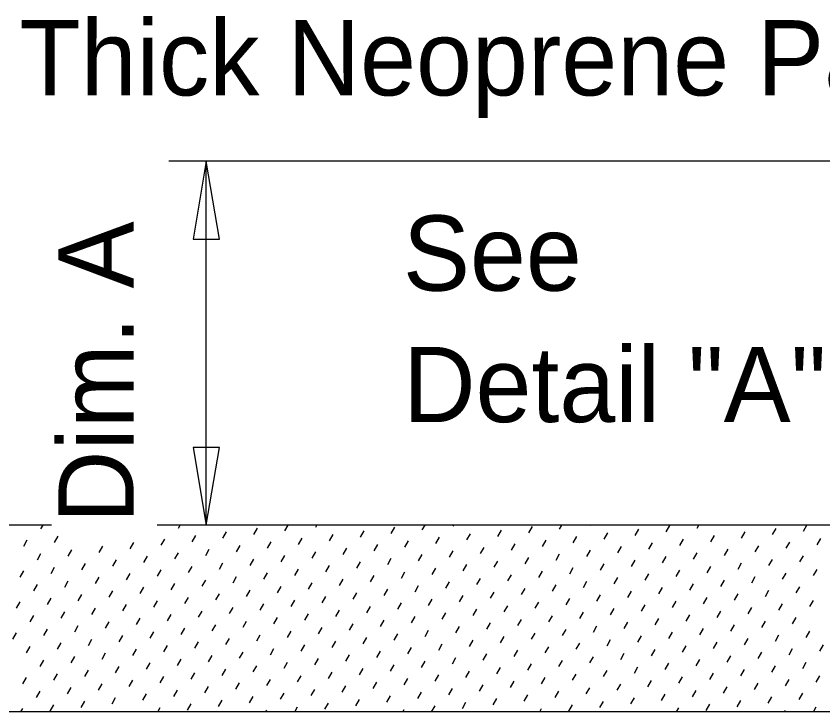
# Model space of a CAD drawing. Extents: x 21516.9 to 21589, y 56156.6 to 56194.3.
# Drawn here: x 21522.743 to 21524.906, y 56182.712 to 56184.575 of the extents above; entities that cross this region are included whole.
import ezdxf

# ---------------------------------------------------------------- set-up
doc = ezdxf.new("R2010")
doc.units = 0
for name, color, linetype in [('AdhocPoint_dp', 7, 'Continuous'), ('Patterning', 7, 'Continuous'), ('PlotBorder_dp', 7, 'Continuous'), ('SheetBorder_dp', 7, 'Continuous')]:
    doc.layers.add(name, color=color, linetype=linetype)

msp = doc.modelspace()

# ---------------------------------------------------------------- linework, layer by layer
at = {"layer": 'AdhocPoint_dp'}
msp.add_line((21525.5524, 56182.7117), (21521.6191, 56182.7117), dxfattribs=at)
at = {"layer": 'Patterning'}
for p, q in [((21522.8378, 56183.2117), (21521.6191, 56183.2117)), ((21522.8099, 56183.2019), (21522.8156, 56183.2117)), ((21525.6112, 56183.2117), (21523.1214, 56183.2117)), ((21523.1783, 56183.2041), (21523.1827, 56183.2117)), ((21523.3808, 56183.187), (21523.3905, 56183.2038)), ((21523.4637, 56183.1967), (21523.4724, 56183.2117)), ((21523.5466, 56183.2064), (21523.5497, 56183.2117)), ((21523.7491, 56183.1893), (21523.7588, 56183.2061)), ((21523.8321, 56183.199), (21523.8394, 56183.2117)), ((21523.915, 56183.2087), (21523.9167, 56183.2117)), ((21524.1175, 56183.1915), (21524.1272, 56183.2083)), ((21524.2004, 56183.2013), (21524.2065, 56183.2117)), ((21524.2833, 56183.211), (21524.2838, 56183.2117)), ((21524.4858, 56183.1938), (21524.4956, 56183.2106)), ((21524.5688, 56183.2035), (21524.5735, 56183.2117)), ((21524.7713, 56183.1864), (21524.781, 56183.2032)), ((21524.8542, 56183.1961), (21524.8632, 56183.2117)), ((21522.8465, 56183.1652), (21522.8562, 56183.182)), ((21523.2149, 56183.1675), (21523.2246, 56183.1843)), ((21523.2978, 56183.1773), (21523.3075, 56183.194)), ((21523.5832, 56183.1698), (21523.593, 56183.1866)), ((21523.6662, 56183.1795), (21523.6759, 56183.1963)), ((21523.9516, 56183.1721), (21523.9613, 56183.1889)), ((21524.0345, 56183.1818), (21524.0443, 56183.1986)), ((21524.237, 56183.1647), (21524.2467, 56183.1814)), ((21524.32, 56183.1744), (21524.3297, 56183.1912)), ((21524.4029, 56183.1841), (21524.4126, 56183.2009)), ((21524.6054, 56183.1669), (21524.6151, 56183.1837)), ((21524.6883, 56183.1767), (21524.698, 56183.1935)), ((21522.7636, 56183.1555), (21522.7733, 56183.1723)), ((21523.049, 56183.1481), (21523.0587, 56183.1649)), ((21523.1319, 56183.1578), (21523.1417, 56183.1746)), ((21523.4174, 56183.1504), (21523.4271, 56183.1672)), ((21523.5003, 56183.1601), (21523.51, 56183.1769)), ((21523.7028, 56183.1429), (21523.7125, 56183.1597)), ((21523.7857, 56183.1526), (21523.7954, 56183.1694)), ((21523.8687, 56183.1624), (21523.8784, 56183.1792)), ((21524.0711, 56183.1452), (21524.0809, 56183.162)), ((21524.1541, 56183.1549), (21524.1638, 56183.1717)), ((21524.4395, 56183.1475), (21524.4492, 56183.1643)), ((21524.5224, 56183.1572), (21524.5322, 56183.174)), ((21524.8079, 56183.1498), (21524.8176, 56183.1666)), ((21524.8908, 56183.1595), (21524.9005, 56183.1763)), ((21522.8831, 56183.1286), (21522.8929, 56183.1454)), ((21522.9661, 56183.1384), (21522.9758, 56183.1552)), ((21523.1685, 56183.1212), (21523.1783, 56183.138)), ((21523.2515, 56183.1309), (21523.2612, 56183.1477)), ((21523.3344, 56183.1406), (21523.3441, 56183.1574)), ((21523.5369, 56183.1235), (21523.5466, 56183.1403)), ((21523.6198, 56183.1332), (21523.6296, 56183.15)), ((21523.9053, 56183.1258), (21523.915, 56183.1426)), ((21523.9882, 56183.1355), (21523.9979, 56183.1523)), ((21524.2736, 56183.128), (21524.2833, 56183.1448)), ((21524.3566, 56183.1378), (21524.3663, 56183.1546)), ((21524.559, 56183.1206), (21524.5688, 56183.1374)), ((21524.642, 56183.1303), (21524.6517, 56183.1471)), ((21524.7249, 56183.1401), (21524.7346, 56183.1568)), ((21522.8002, 56183.1189), (21522.8099, 56183.1357)), ((21523.0027, 56183.1018), (21523.0124, 56183.1185)), ((21523.0856, 56183.1115), (21523.0953, 56183.1283)), ((21523.371, 56183.104), (21523.3808, 56183.1208)), ((21523.454, 56183.1138), (21523.4637, 56183.1306)), ((21523.7394, 56183.1063), (21523.7491, 56183.1231)), ((21523.8223, 56183.116), (21523.8321, 56183.1328)), ((21524.0248, 56183.0989), (21524.0345, 56183.1157)), ((21524.1077, 56183.1086), (21524.1175, 56183.1254)), ((21524.1907, 56183.1183), (21524.2004, 56183.1351)), ((21524.3932, 56183.1012), (21524.4029, 56183.118)), ((21524.4761, 56183.1109), (21524.4858, 56183.1277)), ((21524.7615, 56183.1034), (21524.7713, 56183.1202)), ((21524.8445, 56183.1132), (21524.8542, 56183.13)), ((21522.8368, 56183.0823), (21522.8465, 56183.0991)), ((21522.9197, 56183.092), (21522.9295, 56183.1088)), ((21523.2052, 56183.0846), (21523.2149, 56183.1014)), ((21523.2881, 56183.0943), (21523.2978, 56183.1111)), ((21523.4906, 56183.0772), (21523.5003, 56183.0939)), ((21523.5735, 56183.0869), (21523.5832, 56183.1037)), ((21523.6565, 56183.0966), (21523.6662, 56183.1134)), ((21523.8589, 56183.0794), (21523.8687, 56183.0962)), ((21523.9419, 56183.0892), (21523.9516, 56183.106)), ((21524.2273, 56183.0817), (21524.237, 56183.0985)), ((21524.3102, 56183.0914), (21524.32, 56183.1082)), ((21524.5957, 56183.084), (21524.6054, 56183.1008)), ((21524.6786, 56183.0937), (21524.6883, 56183.1105)), ((21524.8811, 56183.0766), (21524.8908, 56183.0934)), ((21522.7539, 56183.0726), (21522.7636, 56183.0894)), ((21522.9563, 56183.0554), (21522.9661, 56183.0722)), ((21523.0393, 56183.0651), (21523.049, 56183.0819)), ((21523.1222, 56183.0749), (21523.1319, 56183.0917)), ((21523.3247, 56183.0577), (21523.3344, 56183.0745)), ((21523.4076, 56183.0674), (21523.4174, 56183.0842)), ((21523.6931, 56183.06), (21523.7028, 56183.0768)), ((21523.776, 56183.0697), (21523.7857, 56183.0865)), ((21524.0614, 56183.0623), (21524.0711, 56183.0791)), ((21524.1444, 56183.072), (21524.1541, 56183.0888)), ((21524.3468, 56183.0548), (21524.3566, 56183.0716)), ((21524.4298, 56183.0646), (21524.4395, 56183.0813)), ((21524.5127, 56183.0743), (21524.5224, 56183.0911)), ((21524.7152, 56183.0571), (21524.7249, 56183.0739)), ((21524.7981, 56183.0668), (21524.8079, 56183.0836)), ((21522.7905, 56183.036), (21522.8002, 56183.0528)), ((21522.8734, 56183.0457), (21522.8831, 56183.0625)), ((21523.1588, 56183.0383), (21523.1685, 56183.0551)), ((21523.2418, 56183.048), (21523.2515, 56183.0648)), ((21523.5272, 56183.0405), (21523.5369, 56183.0573)), ((21523.6101, 56183.0503), (21523.6198, 56183.0671)), ((21523.8955, 56183.0428), (21523.9053, 56183.0596)), ((21523.9785, 56183.0525), (21523.9882, 56183.0693)), ((21524.181, 56183.0354), (21524.1907, 56183.0522)), ((21524.2639, 56183.0451), (21524.2736, 56183.0619)), ((21524.5493, 56183.0377), (21524.559, 56183.0545)), ((21524.6323, 56183.0474), (21524.642, 56183.0642)), ((21522.993, 56183.0188), (21523.0027, 56183.0356)), ((21523.0759, 56183.0285), (21523.0856, 56183.0453)), ((21523.3613, 56183.0211), (21523.371, 56183.0379)), ((21523.4442, 56183.0308), (21523.454, 56183.0476)), ((21523.6467, 56183.0137), (21523.6565, 56183.0305)), ((21523.7297, 56183.0234), (21523.7394, 56183.0402)), ((21523.8126, 56183.0331), (21523.8223, 56183.0499)), ((21524.0151, 56183.0159), (21524.0248, 56183.0327)), ((21524.098, 56183.0257), (21524.1077, 56183.0425)), ((21524.3834, 56183.0182), (21524.3932, 56183.035)), ((21524.4664, 56183.0279), (21524.4761, 56183.0447)), ((21524.7518, 56183.0205), (21524.7615, 56183.0373)), ((21524.8347, 56183.0302), (21524.8445, 56183.047)), ((21522.8271, 56182.9994), (21522.8368, 56183.0162)), ((21522.91, 56183.0091), (21522.9197, 56183.0259)), ((21523.1125, 56182.9919), (21523.1222, 56183.0087)), ((21523.1954, 56183.0017), (21523.2052, 56183.0184)), ((21523.2784, 56183.0114), (21523.2881, 56183.0282)), ((21523.4809, 56182.9942), (21523.4906, 56183.011)), ((21523.5638, 56183.0039), (21523.5735, 56183.0207)), ((21523.8492, 56182.9965), (21523.8589, 56183.0133)), ((21523.9322, 56183.0062), (21523.9419, 56183.023)), ((21524.2176, 56182.9988), (21524.2273, 56183.0156)), ((21524.3005, 56183.0085), (21524.3102, 56183.0253)), ((21524.503, 56182.9913), (21524.5127, 56183.0081)), ((21524.5859, 56183.0011), (21524.5957, 56183.0179)), ((21524.6689, 56183.0108), (21524.6786, 56183.0276)), ((21524.8713, 56182.9936), (21524.8811, 56183.0104)), ((21522.7441, 56182.9896), (21522.7539, 56183.0064)), ((21522.9466, 56182.9725), (21522.9563, 56182.9893)), ((21523.0296, 56182.9822), (21523.0393, 56182.999)), ((21523.315, 56182.9748), (21523.3247, 56182.9916)), ((21523.3979, 56182.9845), (21523.4076, 56183.0013)), ((21523.6833, 56182.9771), (21523.6931, 56182.9938)), ((21523.7663, 56182.9868), (21523.776, 56183.0036)), ((21523.9688, 56182.9696), (21523.9785, 56182.9864)), ((21524.0517, 56182.9793), (21524.0614, 56182.9961)), ((21524.1346, 56182.9891), (21524.1444, 56183.0059)), ((21524.3371, 56182.9719), (21524.3468, 56182.9887)), ((21524.4201, 56182.9816), (21524.4298, 56182.9984)), ((21524.7055, 56182.9742), (21524.7152, 56182.991)), ((21524.7884, 56182.9839), (21524.7981, 56183.0007)), ((21522.7807, 56182.953), (21522.7905, 56182.9698)), ((21522.8637, 56182.9628), (21522.8734, 56182.9796)), ((21523.1491, 56182.9553), (21523.1588, 56182.9721)), ((21523.232, 56182.965), (21523.2418, 56182.9818)), ((21523.4345, 56182.9479), (21523.4442, 56182.9647)), ((21523.5175, 56182.9576), (21523.5272, 56182.9744)), ((21523.6004, 56182.9673), (21523.6101, 56182.9841)), ((21523.8029, 56182.9502), (21523.8126, 56182.967)), ((21523.8858, 56182.9599), (21523.8955, 56182.9767)), ((21524.1712, 56182.9525), (21524.181, 56182.9692)), ((21524.2542, 56182.9622), (21524.2639, 56182.979)), ((21524.5396, 56182.9547), (21524.5493, 56182.9715)), ((21524.6225, 56182.9645), (21524.6323, 56182.9812)), ((21524.825, 56182.9473), (21524.8347, 56182.9641)), ((21522.9003, 56182.9262), (21522.91, 56182.9429)), ((21522.9832, 56182.9359), (21522.993, 56182.9527)), ((21523.0662, 56182.9456), (21523.0759, 56182.9624)), ((21523.2686, 56182.9284), (21523.2784, 56182.9452)), ((21523.3516, 56182.9382), (21523.3613, 56182.955)), ((21523.637, 56182.9307), (21523.6467, 56182.9475)), ((21523.7199, 56182.9404), (21523.7297, 56182.9572)), ((21524.0054, 56182.933), (21524.0151, 56182.9498)), ((21524.0883, 56182.9427), (21524.098, 56182.9595)), ((21524.2908, 56182.9256), (21524.3005, 56182.9424)), ((21524.3737, 56182.9353), (21524.3834, 56182.9521)), ((21524.4567, 56182.945), (21524.4664, 56182.9618)), ((21524.6591, 56182.9278), (21524.6689, 56182.9446)), ((21524.7421, 56182.9376), (21524.7518, 56182.9544)), ((21522.7344, 56182.9067), (21522.7441, 56182.9235)), ((21522.8174, 56182.9164), (21522.8271, 56182.9332)), ((21523.1028, 56182.909), (21523.1125, 56182.9258)), ((21523.1857, 56182.9187), (21523.1954, 56182.9355)), ((21523.4711, 56182.9113), (21523.4809, 56182.9281)), ((21523.5541, 56182.921), (21523.5638, 56182.9378)), ((21523.7566, 56182.9038), (21523.7663, 56182.9206)), ((21523.8395, 56182.9136), (21523.8492, 56182.9304)), ((21523.9224, 56182.9233), (21523.9322, 56182.9401)), ((21524.1249, 56182.9061), (21524.1346, 56182.9229)), ((21524.2078, 56182.9158), (21524.2176, 56182.9326)), ((21524.4933, 56182.9084), (21524.503, 56182.9252)), ((21524.5762, 56182.9181), (21524.5859, 56182.9349)), ((21524.8616, 56182.9107), (21524.8713, 56182.9275)), ((21522.9369, 56182.8895), (21522.9466, 56182.9063)), ((21523.0198, 56182.8993), (21523.0296, 56182.9161)), ((21523.2223, 56182.8821), (21523.232, 56182.8989)), ((21523.3053, 56182.8918), (21523.315, 56182.9086)), ((21523.3882, 56182.9016), (21523.3979, 56182.9183)), ((21523.5907, 56182.8844), (21523.6004, 56182.9012)), ((21523.6736, 56182.8941), (21523.6833, 56182.9109)), ((21523.959, 56182.8867), (21523.9688, 56182.9035)), ((21524.042, 56182.8964), (21524.0517, 56182.9132)), ((21524.3274, 56182.889), (21524.3371, 56182.9058)), ((21524.4103, 56182.8987), (21524.4201, 56182.9155)), ((21524.6958, 56182.8912), (21524.7055, 56182.908)), ((21524.7787, 56182.901), (21524.7884, 56182.9178)), ((21522.771, 56182.8701), (21522.7807, 56182.8869)), ((21522.854, 56182.8798), (21522.8637, 56182.8966)), ((21523.0564, 56182.8627), (21523.0662, 56182.8795)), ((21523.1394, 56182.8724), (21523.1491, 56182.8892)), ((21523.4248, 56182.8649), (21523.4345, 56182.8817)), ((21523.5077, 56182.8747), (21523.5175, 56182.8915)), ((21523.7932, 56182.8672), (21523.8029, 56182.884)), ((21523.8761, 56182.877), (21523.8858, 56182.8937)), ((21524.1615, 56182.8695), (21524.1712, 56182.8863)), ((21524.2445, 56182.8792), (21524.2542, 56182.896)), ((21524.4469, 56182.8621), (21524.4567, 56182.8789)), ((21524.5299, 56182.8718), (21524.5396, 56182.8886)), ((21524.6128, 56182.8815), (21524.6225, 56182.8983)), ((21524.8153, 56182.8644), (21524.825, 56182.8812)), ((21524.8982, 56182.8741), (21524.908, 56182.8909)), ((21522.8906, 56182.8432), (21522.9003, 56182.86)), ((21522.9735, 56182.8529), (21522.9832, 56182.8697)), ((21523.2589, 56182.8455), (21523.2686, 56182.8623)), ((21523.3419, 56182.8552), (21523.3516, 56182.872)), ((21523.6273, 56182.8478), (21523.637, 56182.8646)), ((21523.7102, 56182.8575), (21523.7199, 56182.8743)), ((21523.9127, 56182.8403), (21523.9224, 56182.8571)), ((21523.9956, 56182.8501), (21524.0054, 56182.8669)), ((21524.0786, 56182.8598), (21524.0883, 56182.8766)), ((21524.2811, 56182.8426), (21524.2908, 56182.8594)), ((21524.364, 56182.8524), (21524.3737, 56182.8691)), ((21524.6494, 56182.8449), (21524.6591, 56182.8617)), ((21524.7324, 56182.8546), (21524.7421, 56182.8714)), ((21522.8076, 56182.8335), (21522.8174, 56182.8503)), ((21523.0931, 56182.8261), (21523.1028, 56182.8428)), ((21523.176, 56182.8358), (21523.1857, 56182.8526)), ((21523.3785, 56182.8186), (21523.3882, 56182.8354)), ((21523.4614, 56182.8283), (21523.4711, 56182.8451)), ((21523.5443, 56182.8381), (21523.5541, 56182.8549)), ((21523.7468, 56182.8209), (21523.7566, 56182.8377)), ((21523.8298, 56182.8306), (21523.8395, 56182.8474)), ((21524.1152, 56182.8232), (21524.1249, 56182.84)), ((21524.1981, 56182.8329), (21524.2078, 56182.8497)), ((21524.4835, 56182.8255), (21524.4933, 56182.8423)), ((21524.5665, 56182.8352), (21524.5762, 56182.852)), ((21524.769, 56182.818), (21524.7787, 56182.8348)), ((21524.8519, 56182.8277), (21524.8616, 56182.8445)), ((21522.8442, 56182.7969), (21522.854, 56182.8137)), ((21522.9272, 56182.8066), (21522.9369, 56182.8234)), ((21523.0101, 56182.8163), (21523.0198, 56182.8331)), ((21523.2126, 56182.7992), (21523.2223, 56182.816)), ((21523.2955, 56182.8089), (21523.3053, 56182.8257)), ((21523.581, 56182.8015), (21523.5907, 56182.8182)), ((21523.6639, 56182.8112), (21523.6736, 56182.828)), ((21523.9493, 56182.8037), (21523.959, 56182.8205)), ((21524.0322, 56182.8135), (21524.042, 56182.8303)), ((21524.2347, 56182.7963), (21524.2445, 56182.8131)), ((21524.3177, 56182.806), (21524.3274, 56182.8228)), ((21524.4006, 56182.8157), (21524.4103, 56182.8325)), ((21524.6031, 56182.7986), (21524.6128, 56182.8154)), ((21524.686, 56182.8083), (21524.6958, 56182.8251)), ((21522.7613, 56182.7872), (21522.771, 56182.804)), ((21523.0467, 56182.7797), (21523.0564, 56182.7965)), ((21523.1297, 56182.7894), (21523.1394, 56182.8062)), ((21523.4151, 56182.782), (21523.4248, 56182.7988)), ((21523.498, 56182.7917), (21523.5077, 56182.8085)), ((21523.7005, 56182.7746), (21523.7102, 56182.7914)), ((21523.7834, 56182.7843), (21523.7932, 56182.8011)), ((21523.8664, 56182.794), (21523.8761, 56182.8108)), ((21524.0689, 56182.7769), (21524.0786, 56182.7936)), ((21524.1518, 56182.7866), (21524.1615, 56182.8034)), ((21524.4372, 56182.7791), (21524.4469, 56182.7959)), ((21524.5202, 56182.7889), (21524.5299, 56182.8057)), ((21524.8056, 56182.7814), (21524.8153, 56182.7982)), ((21524.8885, 56182.7911), (21524.8982, 56182.8079)), ((21522.8808, 56182.7603), (21522.8906, 56182.7771)), ((21522.9638, 56182.77), (21522.9735, 56182.7868)), ((21523.1663, 56182.7528), (21523.176, 56182.7696)), ((21523.2492, 56182.7626), (21523.2589, 56182.7794)), ((21523.3321, 56182.7723), (21523.3419, 56182.7891)), ((21523.5346, 56182.7551), (21523.5443, 56182.7719)), ((21523.6176, 56182.7648), (21523.6273, 56182.7816)), ((21523.903, 56182.7574), (21523.9127, 56182.7742)), ((21523.9859, 56182.7671), (21523.9956, 56182.7839)), ((21524.2713, 56182.7597), (21524.2811, 56182.7765)), ((21524.3543, 56182.7694), (21524.364, 56182.7862)), ((21524.5568, 56182.7523), (21524.5665, 56182.769)), ((21524.6397, 56182.762), (21524.6494, 56182.7788)), ((21524.7226, 56182.7717), (21524.7324, 56182.7885)), ((21522.7979, 56182.7506), (21522.8076, 56182.7674)), ((21523.0004, 56182.7334), (21523.0101, 56182.7502)), ((21523.0833, 56182.7431), (21523.0931, 56182.7599)), ((21523.3687, 56182.7357), (21523.3785, 56182.7525)), ((21523.4517, 56182.7454), (21523.4614, 56182.7622)), ((21523.7371, 56182.738), (21523.7468, 56182.7548)), ((21523.82, 56182.7477), (21523.8298, 56182.7645)), ((21524.0225, 56182.7305), (21524.0322, 56182.7473)), ((21524.1055, 56182.7402), (21524.1152, 56182.757)), ((21524.1884, 56182.75), (21524.1981, 56182.7668)), ((21524.3909, 56182.7328), (21524.4006, 56182.7496)), ((21524.4738, 56182.7425), (21524.4835, 56182.7593)), ((21524.7592, 56182.7351), (21524.769, 56182.7519)), ((21524.8422, 56182.7448), (21524.8519, 56182.7616)), ((21522.8345, 56182.7139), (21522.8442, 56182.7307)), ((21522.9175, 56182.7237), (21522.9272, 56182.7405)), ((21523.2029, 56182.7162), (21523.2126, 56182.733)), ((21523.2858, 56182.726), (21523.2955, 56182.7427)), ((21523.49, 56182.7117), (21523.498, 56182.7256)), ((21523.5712, 56182.7185), (21523.581, 56182.7353)), ((21523.6542, 56182.7282), (21523.6639, 56182.745)), ((21523.857, 56182.7117), (21523.8664, 56182.7279)), ((21523.9396, 56182.7208), (21523.9493, 56182.7376)), ((21524.225, 56182.7134), (21524.2347, 56182.7302)), ((21524.3079, 56182.7231), (21524.3177, 56182.7399)), ((21524.5934, 56182.7156), (21524.6031, 56182.7324)), ((21524.6763, 56182.7254), (21524.686, 56182.7422)), ((21522.7559, 56182.7117), (21522.7613, 56182.721)), ((21523.0457, 56182.7117), (21523.0467, 56182.7136)), ((21523.123, 56182.7117), (21523.1297, 56182.7233)), ((21523.4127, 56182.7117), (21523.4151, 56182.7159)), ((21523.7797, 56182.7117), (21523.7834, 56182.7181)), ((21524.1468, 56182.7117), (21524.1518, 56182.7204)), ((21524.4365, 56182.7117), (21524.4372, 56182.713)), ((21524.5138, 56182.7117), (21524.5202, 56182.7227)), ((21524.8035, 56182.7117), (21524.8056, 56182.7153)), ((21524.8808, 56182.7117), (21524.8885, 56182.725))]:
    msp.add_line(p, q, dxfattribs=at)
at = {"layer": 'PlotBorder_dp'}
for p, q in [((21525.65, 56184.1864), (21523.1528, 56184.1864)), ((21523.2529, 56183.2118), (21523.2529, 56184.1864))]:
    msp.add_line(p, q, dxfattribs=at)
for points in [[(21523.2529, 56184.1864), (21523.2176, 56183.9781), (21523.2881, 56183.9781)], [(21523.2529, 56183.2118), (21523.2881, 56183.42), (21523.2176, 56183.42)]]:
    msp.add_lwpolyline(points, close=True, dxfattribs=at)

# ---------------------------------------------------------------- texts
msp.add_text('Thick Neoprene Pad', height=0.2016, dxfattribs=at).set_placement((21522.7517, 56184.3628))
at = {"layer": 'SheetBorder_dp'}
msp.add_text('Dim. A', height=0.2016, rotation=90, dxfattribs=at).set_placement((21523.0582, 56183.2169))
for s, p in [('See ', (21523.7802, 56183.8398)), ('Detail "A" ', (21523.7802, 56183.4878))]:
    msp.add_text(s, height=0.2016, dxfattribs=at).set_placement(p)

doc.saveas('drawing.dxf')
